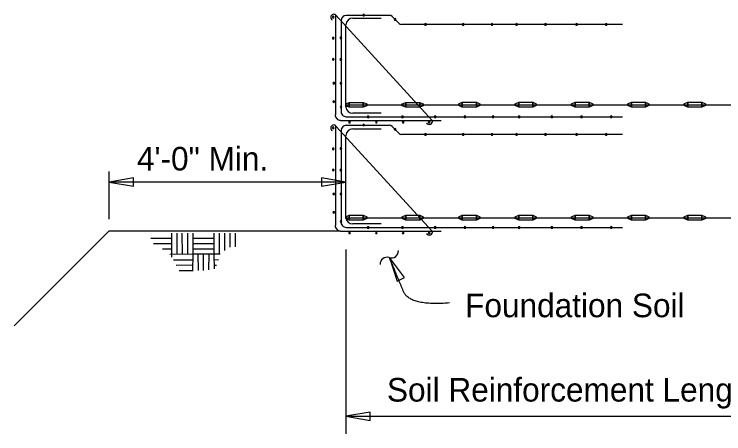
# Model space of a CAD drawing. Extents: x 126777.1 to 126780.68, y 176294.14 to 176295.44.
# Drawn here: x 126779.1525 to 126779.3418, y 176295.0005 to 176295.1124 of the extents above; entities that cross this region are included whole.
import ezdxf

# ---------------------------------------------------------------- set-up
doc = ezdxf.new("R2010")
doc.units = 0
for name, color, linetype in [('AdhocPoint_dp', 7, 'Continuous'), ('Miscellaneous', 7, 'Continuous'), ('Patterning', 7, 'Continuous'), ('SteelMisc_h', 7, 'Continuous'), ('TextMisc', 7, 'Continuous')]:
    doc.layers.add(name, color=color, linetype=linetype)

msp = doc.modelspace()

# ---------------------------------------------------------------- linework, layer by layer
at = {"layer": 'AdhocPoint_dp'}
for p, q in [((126779.1777941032, 176295.05770833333), (126779.1777941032, 176295.07041666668)), ((126779.24097118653, 176295.06760416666), (126779.1777941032, 176295.06760416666)), ((126779.15246921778, 176295.02924738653), (126779.17778786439, 176295.05456603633)), ((126779.23956493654, 176295.05453125), (126779.1777941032, 176295.05453125)), ((126779.24097118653, 176295.04963541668), (126779.24097118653, 176295.00046875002)), ((126779.24097118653, 176295.00515625), (126779.38456493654, 176295.00515625))]:
    msp.add_line(p, q, dxfattribs=at)
for points in [[(126779.1777941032, 176295.06760416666), (126779.1843020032, 176295.06650166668), (126779.1843020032, 176295.06870666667)], [(126779.24097118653, 176295.06760416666), (126779.23446328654, 176295.06870666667), (126779.23446328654, 176295.06650166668)], [(126779.25258576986, 176295.04744791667), (126779.25463177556, 176295.04117243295), (126779.25658454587, 176295.0421964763)], [(126779.24097118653, 176295.00515625), (126779.24747908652, 176295.00405375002), (126779.24747908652, 176295.00625875)]]:
    msp.add_lwpolyline(points, close=True, dxfattribs=at)
for centre, radius, start, end in [((126779.25311525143, 176295.04923394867), 0.00186293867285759, 251.85215555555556, 3.5793750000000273), ((126779.25195475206, 176295.04569341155), 0.001862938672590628, 71.85215555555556, 183.57937500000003)]:
    msp.add_arc(centre, radius, start, end, dxfattribs=at)
msp.add_open_spline([(126779.26858292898, 176295.03536054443), (126779.25792916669, 176295.0344760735), (126779.2546819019, 176295.04245145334), (126779.25255573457, 176295.04747418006)], degree=2, dxfattribs=at)
at = {"layer": 'Miscellaneous'}
for p, q in [((126779.24097118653, 176295.08822916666), (126779.3821691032, 176295.08822916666)), ((126779.24097118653, 176295.05807291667), (126779.3821691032, 176295.05807291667)), ((126779.1945128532, 176295.04833333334), (126779.1945128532, 176295.05395833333)), ((126779.19591910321, 176295.04833333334), (126779.19597118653, 176295.05395833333)), ((126779.19737743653, 176295.04828125), (126779.1973253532, 176295.05395833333)), ((126779.19878368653, 176295.04833333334), (126779.19878368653, 176295.05395833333)), ((126779.20018993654, 176295.04833333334), (126779.20018993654, 176295.05395833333)), ((126779.20581493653, 176295.04833333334), (126779.20581493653, 176295.05401041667)), ((126779.20727326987, 176295.04828125), (126779.20727326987, 176295.05395833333)), ((126779.20867951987, 176295.049375), (126779.20862743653, 176295.05395833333)), ((126779.21008576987, 176295.05020833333), (126779.21008576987, 176295.05401041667)), ((126779.21154410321, 176295.0503125), (126779.21149201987, 176295.05395833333)), ((126779.1945128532, 176295.05255208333), (126779.1888878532, 176295.05255208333)), ((126779.19456493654, 176295.05114583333), (126779.18961701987, 176295.05114583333)), ((126779.20581493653, 176295.05255208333), (126779.20018993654, 176295.05255208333)), ((126779.20586701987, 176295.05109375), (126779.20018993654, 176295.05114583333)), ((126779.1945128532, 176295.04973958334), (126779.19201285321, 176295.04973958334)), ((126779.20581493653, 176295.04973958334), (126779.20018993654, 176295.0496875)), ((126779.20018993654, 176295.04833333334), (126779.19399201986, 176295.04828125)), ((126779.1945128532, 176295.04760416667), (126779.1945128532, 176295.04833333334)), ((126779.2001378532, 176295.04390625), (126779.20018993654, 176295.04833333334)), ((126779.20742951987, 176295.04833333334), (126779.20018993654, 176295.04833333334)), ((126779.20159618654, 176295.0440625), (126779.2015441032, 176295.04833333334)), ((126779.20300243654, 176295.0440625), (126779.20300243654, 176295.04833333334)), ((126779.20440868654, 176295.04421875), (126779.20446076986, 176295.04833333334)), ((126779.20586701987, 176295.04447916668), (126779.20581493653, 176295.04833333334)), ((126779.19492951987, 176295.046875), (126779.20018993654, 176295.046875)), ((126779.19565868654, 176295.04546875), (126779.20018993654, 176295.04552083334)), ((126779.20581493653, 176295.04546875), (126779.20643993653, 176295.04546875)), ((126779.20586701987, 176295.046875), (126779.20696076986, 176295.04692708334)), ((126779.19643993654, 176295.0440625), (126779.20018993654, 176295.0440625))]:
    msp.add_line(p, q, dxfattribs=at)
for points in [[(126779.2710753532, 176295.0884375), (126779.2720128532, 176295.08890625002), (126779.2720128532, 176295.08755208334), (126779.2710753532, 176295.08802083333)], [(126779.2720128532, 176295.08890625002), (126779.2757628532, 176295.08890625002), (126779.2757628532, 176295.08755208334), (126779.2720128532, 176295.08755208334)], [(126779.2757628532, 176295.08890625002), (126779.2767003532, 176295.0884375), (126779.2767003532, 176295.08802083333), (126779.2757628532, 176295.08755208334)], [(126779.28612743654, 176295.0884375), (126779.28706493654, 176295.08890625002), (126779.28706493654, 176295.08755208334), (126779.28612743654, 176295.08802083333)], [(126779.28706493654, 176295.08890625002), (126779.29081493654, 176295.08890625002), (126779.29081493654, 176295.08755208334), (126779.28706493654, 176295.08755208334)], [(126779.29081493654, 176295.08890625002), (126779.29175243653, 176295.0884375), (126779.29175243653, 176295.08802083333), (126779.29081493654, 176295.08755208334)], [(126779.30112743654, 176295.0884375), (126779.30211701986, 176295.08890625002), (126779.30211701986, 176295.08755208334), (126779.30112743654, 176295.08802083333)], [(126779.30211701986, 176295.08890625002), (126779.30586701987, 176295.08890625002), (126779.30586701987, 176295.08755208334), (126779.30211701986, 176295.08755208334)], [(126779.30586701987, 176295.08890625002), (126779.30680451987, 176295.0884375), (126779.30680451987, 176295.08802083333), (126779.30586701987, 176295.08755208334)], [(126779.31617951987, 176295.0884375), (126779.31711701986, 176295.08890625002), (126779.31711701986, 176295.08755208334), (126779.31617951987, 176295.08802083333)], [(126779.31711701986, 176295.08890625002), (126779.32086701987, 176295.08890625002), (126779.32086701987, 176295.08755208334), (126779.31711701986, 176295.08755208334)], [(126779.32086701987, 176295.08890625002), (126779.32180451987, 176295.0884375), (126779.32180451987, 176295.08802083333), (126779.32086701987, 176295.08755208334)], [(126779.3312316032, 176295.0884375), (126779.3321691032, 176295.08890625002), (126779.3321691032, 176295.08755208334), (126779.3312316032, 176295.08802083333)], [(126779.3321691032, 176295.08890625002), (126779.3359191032, 176295.08890625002), (126779.3359191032, 176295.08755208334), (126779.3321691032, 176295.08755208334)], [(126779.3359191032, 176295.08890625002), (126779.3368566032, 176295.0884375), (126779.3368566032, 176295.08802083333), (126779.3359191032, 176295.08755208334)], [(126779.2409191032, 176295.0884375), (126779.2418566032, 176295.08885416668), (126779.2418566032, 176295.08755208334), (126779.2409191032, 176295.08796875)], [(126779.2418566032, 176295.08885416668), (126779.2456066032, 176295.08885416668), (126779.2456066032, 176295.08755208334), (126779.2418566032, 176295.08755208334)], [(126779.2456066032, 176295.08885416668), (126779.2465441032, 176295.0884375), (126779.2465441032, 176295.08796875), (126779.2456066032, 176295.08755208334)], [(126779.25597118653, 176295.0884375), (126779.25690868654, 176295.08885416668), (126779.25690868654, 176295.08755208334), (126779.25597118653, 176295.08796875)], [(126779.25690868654, 176295.08885416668), (126779.26065868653, 176295.08885416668), (126779.26065868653, 176295.08755208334), (126779.25690868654, 176295.08755208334)], [(126779.26065868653, 176295.08885416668), (126779.26159618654, 176295.0884375), (126779.26159618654, 176295.08796875), (126779.26065868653, 176295.08755208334)], [(126779.2409191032, 176295.05833333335), (126779.2418566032, 176295.05875), (126779.2418566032, 176295.05744791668), (126779.2409191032, 176295.05786458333)], [(126779.2418566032, 176295.05875), (126779.2456066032, 176295.05875), (126779.2456066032, 176295.05744791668), (126779.2418566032, 176295.05744791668)], [(126779.2456066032, 176295.05875), (126779.2465441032, 176295.05833333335), (126779.2465441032, 176295.05786458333), (126779.2456066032, 176295.05744791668)], [(126779.25597118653, 176295.05833333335), (126779.25690868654, 176295.05875), (126779.25690868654, 176295.05744791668), (126779.25597118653, 176295.05786458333)], [(126779.25690868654, 176295.05875), (126779.26065868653, 176295.05875), (126779.26065868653, 176295.05744791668), (126779.25690868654, 176295.05744791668)], [(126779.26065868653, 176295.05875), (126779.26159618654, 176295.05833333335), (126779.26159618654, 176295.05786458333), (126779.26065868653, 176295.05744791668)], [(126779.2710753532, 176295.05833333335), (126779.2720128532, 176295.05875), (126779.2720128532, 176295.05744791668), (126779.2710753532, 176295.05791666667)], [(126779.2720128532, 176295.05875), (126779.2757628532, 176295.05875), (126779.2757628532, 176295.05744791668), (126779.2720128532, 176295.05744791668)], [(126779.2757628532, 176295.05875), (126779.2767003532, 176295.05833333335), (126779.2767003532, 176295.05791666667), (126779.2757628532, 176295.05744791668)], [(126779.28612743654, 176295.05833333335), (126779.28706493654, 176295.05875), (126779.28706493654, 176295.05744791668), (126779.28612743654, 176295.05791666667)], [(126779.28706493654, 176295.05875), (126779.29081493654, 176295.05875), (126779.29081493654, 176295.05744791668), (126779.28706493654, 176295.05744791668)], [(126779.29081493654, 176295.05875), (126779.29175243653, 176295.05833333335), (126779.29175243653, 176295.05791666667), (126779.29081493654, 176295.05744791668)], [(126779.30112743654, 176295.05833333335), (126779.30211701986, 176295.05875), (126779.30211701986, 176295.05744791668), (126779.30112743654, 176295.05791666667)], [(126779.30211701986, 176295.05875), (126779.30586701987, 176295.05875), (126779.30586701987, 176295.05744791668), (126779.30211701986, 176295.05744791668)], [(126779.30586701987, 176295.05875), (126779.30680451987, 176295.05833333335), (126779.30680451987, 176295.05791666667), (126779.30586701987, 176295.05744791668)], [(126779.31617951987, 176295.05833333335), (126779.31711701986, 176295.05875), (126779.31711701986, 176295.05744791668), (126779.31617951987, 176295.05791666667)], [(126779.31711701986, 176295.05875), (126779.32086701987, 176295.05875), (126779.32086701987, 176295.05744791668), (126779.31711701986, 176295.05744791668)], [(126779.32086701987, 176295.05875), (126779.32180451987, 176295.05833333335), (126779.32180451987, 176295.05791666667), (126779.32086701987, 176295.05744791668)], [(126779.3312316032, 176295.05833333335), (126779.3321691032, 176295.05875), (126779.3321691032, 176295.05744791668), (126779.3312316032, 176295.05791666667)], [(126779.3321691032, 176295.05875), (126779.3359191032, 176295.05875), (126779.3359191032, 176295.05744791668), (126779.3321691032, 176295.05744791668)], [(126779.3359191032, 176295.05875), (126779.3368566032, 176295.05833333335), (126779.3368566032, 176295.05791666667), (126779.3359191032, 176295.05744791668)]]:
    msp.add_lwpolyline(points, close=True, dxfattribs=at)
at = {"layer": 'Patterning'}
for p, q in [((126779.23815868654, 176295.11223958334), (126779.23815868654, 176295.08552083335)), ((126779.26399201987, 176295.0840625), (126779.23831493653, 176295.11208333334)), ((126779.2526378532, 176295.11203125), (126779.2410753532, 176295.11203125)), ((126779.25513785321, 176295.10989583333), (126779.2532628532, 176295.11177083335)), ((126779.2396691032, 176295.11067708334), (126779.2396691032, 176295.08651041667)), ((126779.31477326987, 176295.10958333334), (126779.25581493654, 176295.10958333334)), ((126779.23956493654, 176295.0840625), (126779.26633576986, 176295.0840625)), ((126779.2410753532, 176295.08500000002), (126779.31477326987, 176295.08500000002)), ((126779.23815868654, 176295.08270833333), (126779.23815868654, 176295.05598958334)), ((126779.26399201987, 176295.05453125), (126779.23831493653, 176295.08255208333)), ((126779.2396691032, 176295.08135416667), (126779.2396691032, 176295.05697916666)), ((126779.2526378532, 176295.08270833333), (126779.2410753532, 176295.08270833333)), ((126779.25513785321, 176295.08057291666), (126779.2532628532, 176295.08244791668)), ((126779.31477326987, 176295.08026041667), (126779.25581493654, 176295.08026041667)), ((126779.2410753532, 176295.05546875), (126779.31477326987, 176295.05546875)), ((126779.23956493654, 176295.05453125), (126779.26633576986, 176295.05453125))]:
    msp.add_line(p, q, dxfattribs=at)
for centre, radius, start, end in [((126779.23773540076, 176295.1115304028), 0.0008108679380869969, 46.772822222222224, 237.35298333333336), ((126779.2375912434, 176295.1116010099), 0.00023464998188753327, 0, 180), ((126779.2375912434, 176295.1116010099), 0.00023464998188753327, 180, 0), ((126779.24106948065, 176295.11065462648), 0.0014092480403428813, 90, 176.86310555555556), ((126779.24569643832, 176295.11213749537), 0.00023464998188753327, 0, 180), ((126779.24569643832, 176295.11213749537), 0.00023464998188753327, 180, 0), ((126779.2526067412, 176295.11112437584), 0.0009394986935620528, 45, 90), ((126779.25407553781, 176295.11098423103), 0.00023464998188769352, 0, 180), ((126779.25407553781, 176295.11098423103), 0.00023464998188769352, 180, 0), ((126779.25580658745, 176295.11058183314), 0.000939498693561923, 225, 270), ((126779.26219822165, 176295.1096423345), 0.0002346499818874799, 0, 180), ((126779.27223601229, 176295.1096423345), 0.00023464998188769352, 0, 180), ((126779.27994415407, 176295.1096423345), 0.0002346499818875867, 0, 180), ((126779.28650547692, 176295.1096423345), 0.00023464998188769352, 0, 180), ((126779.2942136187, 176295.1096423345), 0.0002346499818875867, 0, 180), ((126779.30249415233, 176295.1096423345), 0.00023464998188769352, 0, 180), ((126779.31041589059, 176295.1096423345), 0.00023464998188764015, 0, 180), ((126779.26219822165, 176295.1096423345), 0.0002346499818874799, 180, 0), ((126779.27223601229, 176295.1096423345), 0.00023464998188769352, 180, 0), ((126779.27994415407, 176295.1096423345), 0.0002346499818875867, 180, 0), ((126779.28650547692, 176295.1096423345), 0.00023464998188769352, 180, 0), ((126779.2942136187, 176295.1096423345), 0.0002346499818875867, 180, 0), ((126779.30249415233, 176295.1096423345), 0.00023464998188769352, 180, 0), ((126779.31041589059, 176295.1096423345), 0.00023464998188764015, 180, 0), ((126779.2375912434, 176295.10596401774), 0.00023464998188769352, 0, 180), ((126779.2375912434, 176295.10596401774), 0.00023464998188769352, 180, 0), ((126779.23962900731, 176295.10604083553), 0.00023464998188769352, 0, 180), ((126779.23962900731, 176295.10604083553), 0.00023464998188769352, 180, 0), ((126779.2375912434, 176295.1003270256), 0.00023464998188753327, 0, 180), ((126779.2375912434, 176295.1003270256), 0.00023464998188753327, 180, 0), ((126779.23961822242, 176295.10031537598), 0.00023464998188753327, 0, 180), ((126779.23961822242, 176295.10031537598), 0.00023464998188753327, 180, 0), ((126779.23771990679, 176295.09394764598), 0.00023464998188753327, 0, 180), ((126779.23771990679, 176295.09394764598), 0.00023464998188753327, 180, 0), ((126779.23962869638, 176295.09393289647), 0.00023464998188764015, 0, 180), ((126779.23962869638, 176295.09393289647), 0.00023464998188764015, 180, 0), ((126779.23771990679, 176295.08905304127), 0.00023464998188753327, 0, 180), ((126779.23771990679, 176295.08905304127), 0.00023464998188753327, 180, 0), ((126779.23964379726, 176295.0875654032), 0.00023464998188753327, 0, 180), ((126779.23964379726, 176295.0875654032), 0.00023464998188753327, 180, 0), ((126779.23952640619, 176295.0854883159), 0.0014092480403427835, 176.94386666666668, 270), ((126779.24106667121, 176295.08645222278), 0.0014092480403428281, 176.86310555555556, 270), ((126779.24689499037, 176295.08498519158), 0.00023464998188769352, 0, 180), ((126779.25606069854, 176295.08498519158), 0.00023464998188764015, 0, 180), ((126779.26478414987, 176295.08502284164), 0.00023464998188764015, 0, 180), ((126779.27270588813, 176295.08502284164), 0.00023464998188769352, 0, 180), ((126779.28023493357, 176295.08502284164), 0.00023464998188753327, 0, 180), ((126779.28717844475, 176295.08498519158), 0.00023464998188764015, 0, 180), ((126779.29590189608, 176295.08502284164), 0.00023464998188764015, 0, 180), ((126779.30382363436, 176295.08502284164), 0.00023464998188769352, 0, 180), ((126779.31174537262, 176295.08502284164), 0.00023464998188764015, 0, 180), ((126779.2419406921, 176295.08360152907), 0.0002346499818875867, 0, 180), ((126779.2419406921, 176295.08360152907), 0.0002346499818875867, 180, 0), ((126779.24689499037, 176295.08498519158), 0.00023464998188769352, 180, 0), ((126779.24908088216, 176295.08360152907), 0.00023464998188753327, 0, 180), ((126779.24908088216, 176295.08360152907), 0.00023464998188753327, 180, 0), ((126779.25606069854, 176295.08498519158), 0.00023464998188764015, 180, 0), ((126779.25622107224, 176295.08360152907), 0.00023464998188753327, 0, 180), ((126779.25622107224, 176295.08360152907), 0.00023464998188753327, 180, 0), ((126779.26318522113, 176295.08380543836), 0.0008425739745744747, 205.95775833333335, 20.726922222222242), ((126779.26320094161, 176295.08360524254), 0.00023464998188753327, 0, 180), ((126779.26320094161, 176295.08360524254), 0.00023464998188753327, 180, 0), ((126779.26478414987, 176295.08502284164), 0.00023464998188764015, 180, 0), ((126779.27270588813, 176295.08502284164), 0.00023464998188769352, 180, 0), ((126779.28023493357, 176295.08502284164), 0.00023464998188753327, 180, 0), ((126779.28717844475, 176295.08498519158), 0.00023464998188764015, 180, 0), ((126779.29590189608, 176295.08502284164), 0.00023464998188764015, 180, 0), ((126779.30382363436, 176295.08502284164), 0.00023464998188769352, 180, 0), ((126779.31174537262, 176295.08502284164), 0.00023464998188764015, 180, 0), ((126779.23773540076, 176295.08201497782), 0.0008108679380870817, 46.772822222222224, 237.35298333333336), ((126779.2375912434, 176295.0820855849), 0.00023464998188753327, 0, 180), ((126779.2375912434, 176295.0820855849), 0.00023464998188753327, 180, 0), ((126779.24106948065, 176295.08133246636), 0.0014092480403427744, 90, 176.86310555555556), ((126779.24569643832, 176295.0828153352), 0.00023464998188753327, 0, 180), ((126779.24569643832, 176295.0828153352), 0.00023464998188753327, 180, 0), ((126779.2526067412, 176295.0818022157), 0.000939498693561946, 45, 90), ((126779.25407553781, 176295.08166207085), 0.00023464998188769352, 0, 180), ((126779.25407553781, 176295.08166207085), 0.00023464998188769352, 180, 0), ((126779.25580658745, 176295.08125967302), 0.000939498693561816, 225, 270), ((126779.26219822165, 176295.08032017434), 0.0002346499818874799, 0, 180), ((126779.26219822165, 176295.08032017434), 0.0002346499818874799, 180, 0), ((126779.27223601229, 176295.08032017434), 0.00023464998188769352, 0, 180), ((126779.27223601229, 176295.08032017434), 0.00023464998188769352, 180, 0), ((126779.27994415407, 176295.08032017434), 0.0002346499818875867, 0, 180), ((126779.27994415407, 176295.08032017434), 0.0002346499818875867, 180, 0), ((126779.28650547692, 176295.08032017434), 0.00023464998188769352, 0, 180), ((126779.28650547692, 176295.08032017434), 0.00023464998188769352, 180, 0), ((126779.2942136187, 176295.08032017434), 0.0002346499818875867, 0, 180), ((126779.2942136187, 176295.08032017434), 0.0002346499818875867, 180, 0), ((126779.30249415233, 176295.08032017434), 0.00023464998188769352, 0, 180), ((126779.30249415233, 176295.08032017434), 0.00023464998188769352, 180, 0), ((126779.31041589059, 176295.08032017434), 0.00023464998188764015, 0, 180), ((126779.31041589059, 176295.08032017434), 0.00023464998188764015, 180, 0), ((126779.2375912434, 176295.07644859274), 0.00023464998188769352, 0, 180), ((126779.2375912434, 176295.07644859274), 0.00023464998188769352, 180, 0), ((126779.23962900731, 176295.07652541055), 0.00023464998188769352, 0, 180), ((126779.23962900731, 176295.07652541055), 0.00023464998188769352, 180, 0), ((126779.2375912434, 176295.0708116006), 0.00023464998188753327, 0, 180), ((126779.2375912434, 176295.0708116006), 0.00023464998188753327, 180, 0), ((126779.23961822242, 176295.07079995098), 0.00023464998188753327, 0, 180), ((126779.23961822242, 176295.07079995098), 0.00023464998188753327, 180, 0), ((126779.23771990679, 176295.06443222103), 0.00023464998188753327, 0, 180), ((126779.23771990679, 176295.06443222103), 0.00023464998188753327, 180, 0), ((126779.23962869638, 176295.06441747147), 0.00023464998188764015, 0, 180), ((126779.23962869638, 176295.06441747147), 0.00023464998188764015, 180, 0), ((126779.23771990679, 176295.0595376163), 0.00023464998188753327, 0, 180), ((126779.23771990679, 176295.0595376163), 0.00023464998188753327, 180, 0), ((126779.23965688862, 176295.05709702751), 0.0002346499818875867, 0, 180), ((126779.23965688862, 176295.05709702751), 0.0002346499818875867, 180, 0), ((126779.24106664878, 176295.0569367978), 0.0014092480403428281, 176.86310555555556, 270), ((126779.23952640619, 176295.05597289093), 0.0014092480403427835, 176.94386666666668, 270), ((126779.24689499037, 176295.0554697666), 0.00023464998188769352, 0, 180), ((126779.24689499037, 176295.0554697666), 0.00023464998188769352, 180, 0), ((126779.25606069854, 176295.0554697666), 0.00023464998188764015, 0, 180), ((126779.25606069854, 176295.0554697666), 0.00023464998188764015, 180, 0), ((126779.26478414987, 176295.05550741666), 0.00023464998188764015, 0, 180), ((126779.26478414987, 176295.05550741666), 0.00023464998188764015, 180, 0), ((126779.27270588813, 176295.05550741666), 0.00023464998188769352, 0, 180), ((126779.27270588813, 176295.05550741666), 0.00023464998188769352, 180, 0), ((126779.28023493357, 176295.05550741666), 0.00023464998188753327, 0, 180), ((126779.28023493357, 176295.05550741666), 0.00023464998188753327, 180, 0), ((126779.28717844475, 176295.0554697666), 0.00023464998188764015, 0, 180), ((126779.28717844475, 176295.0554697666), 0.00023464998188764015, 180, 0), ((126779.29590189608, 176295.05550741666), 0.00023464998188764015, 0, 180), ((126779.29590189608, 176295.05550741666), 0.00023464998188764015, 180, 0), ((126779.30382363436, 176295.05550741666), 0.00023464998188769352, 0, 180), ((126779.30382363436, 176295.05550741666), 0.00023464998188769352, 180, 0), ((126779.31174537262, 176295.05550741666), 0.00023464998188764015, 0, 180), ((126779.31174537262, 176295.05550741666), 0.00023464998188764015, 180, 0), ((126779.2419406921, 176295.05408610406), 0.0002346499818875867, 0, 180), ((126779.2419406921, 176295.05408610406), 0.0002346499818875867, 180, 0), ((126779.24908088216, 176295.05408610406), 0.00023464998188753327, 0, 180), ((126779.24908088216, 176295.05408610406), 0.00023464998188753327, 180, 0), ((126779.25622107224, 176295.05408610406), 0.00023464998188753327, 0, 180), ((126779.25622107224, 176295.05408610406), 0.00023464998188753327, 180, 0), ((126779.26318522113, 176295.05429001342), 0.0008425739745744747, 205.95775833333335, 20.726922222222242), ((126779.26320094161, 176295.05408981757), 0.00023464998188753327, 0, 180), ((126779.26320094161, 176295.05408981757), 0.00023464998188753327, 180, 0)]:
    msp.add_arc(centre, radius, start, end, dxfattribs=at)
at = {"layer": 'SteelMisc_h'}
for p, q in [((126779.24284618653, 176295.11130208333), (126779.25034618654, 176295.11130208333)), ((126779.24097118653, 176295.08760416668), (126779.24097118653, 176295.10953125)), ((126779.25034618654, 176295.0859375), (126779.24279410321, 176295.0859375)), ((126779.24284618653, 176295.08177083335), (126779.25034618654, 176295.08177083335)), ((126779.24097118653, 176295.058125), (126779.24097118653, 176295.08000000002)), ((126779.25034618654, 176295.05645833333), (126779.24279410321, 176295.05645833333))]:
    msp.add_line(p, q, dxfattribs=at)
for centre, radius, start, end in [((126779.24283708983, 176295.10943864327), 0.0018789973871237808, 90, 176.86310555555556), ((126779.24280248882, 176295.08786147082), 0.0018789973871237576, 186.41944166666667, 270), ((126779.24283708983, 176295.07992321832), 0.0018789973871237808, 90, 176.86310555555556), ((126779.24280248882, 176295.05834604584), 0.0018789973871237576, 186.41944166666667, 270)]:
    msp.add_arc(centre, radius, start, end, dxfattribs=at)

# ---------------------------------------------------------------- texts
at = {"layer": 'TextMisc'}
for s, p in [('4\'-0" Min.', (126779.1852122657, 176295.07068522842)), ('Foundation Soil', (126779.27276948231, 176295.0315627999)), ('Soil Reinforcement Length', (126779.25191689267, 176295.00906264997))]:
    msp.add_text(s, height=0.0063000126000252, dxfattribs=at).set_placement(p)

doc.saveas('drawing.dxf')
